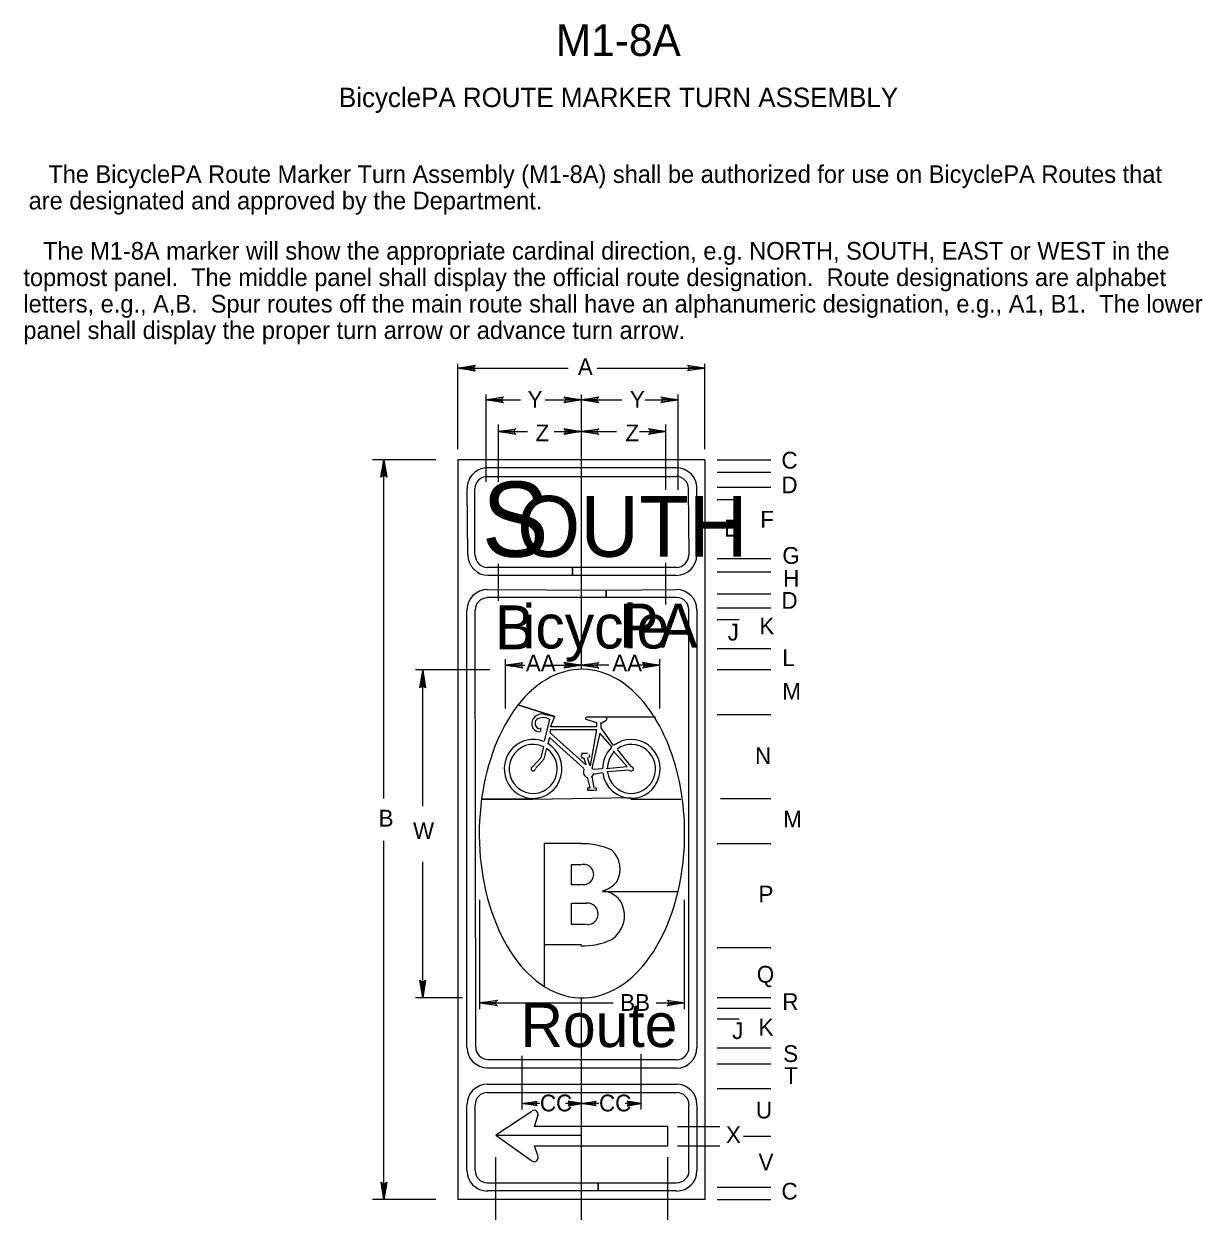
# Model space of a CAD drawing. Extents: x 0.013 to 0.193, y 0.004 to 0.259.
# Drawn here: x 0.0257 to 0.1928, y 0.091 to 0.2593 of the extents above; entities that cross this region are included whole.
import ezdxf

# ---------------------------------------------------------------- set-up
doc = ezdxf.new("R2010")
doc.units = 0
for name, color, linetype in [('1', 7, 'Continuous'), ('2', 7, 'Continuous'), ('3', 7, 'Continuous')]:
    doc.layers.add(name, color=color, linetype=linetype)

# ---------------------------------------------------------------- blocks, each defined once
blk = doc.blocks.new('RARROW')
at = {"layer": '3'}
for p, q in [((-2.156, 0.28500000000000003), (-2.2665, 0.384625)), ((-2.2665, 0.384625), (0, 0)), ((0, 0), (-2.2665, -0.379125)), ((-2.156, 0.28500000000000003), (-2.075625, 0.12075)), ((0, 0), (-2.156, 0.28500000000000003)), ((-2.14975, -0.2705), (0, 0)), ((-2.075625, 0.12075), (0, 0)), ((0, 0), (-2.074, -0.108)), ((-2.2665, -0.379125), (-2.14975, -0.2705)), ((-2.074, -0.108), (-2.14975, -0.2705))]:
    blk.add_line(p, q, dxfattribs=at)

msp = doc.modelspace()

# ---------------------------------------------------------------- linework, layer by layer
at = {"layer": '3'}
for p, q in [((0.08725000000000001, 0.199), (0.08725000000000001, 0.211125)), ((0.08725000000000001, 0.2105), (0.10287500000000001, 0.2105)), ((0.107, 0.2105), (0.12225, 0.2105)), ((0.12225, 0.199), (0.12225, 0.211125)), ((0.09125, 0.194375), (0.09125, 0.20675000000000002)), ((0.09125, 0.20600000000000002), (0.096125, 0.20600000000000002)), ((0.099625, 0.20600000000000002), (0.10475, 0.20600000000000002)), ((0.10475, 0.199875), (0.10475, 0.20675000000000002)), ((0.10475, 0.20600000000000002), (0.1105, 0.20600000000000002)), ((0.11375, 0.20600000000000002), (0.11850000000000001, 0.20600000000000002)), ((0.11850000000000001, 0.19325), (0.11850000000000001, 0.20675000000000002)), ((0.093, 0.194375), (0.093, 0.2025)), ((0.11675, 0.19325), (0.11675, 0.2025)), ((0.093, 0.2015), (0.097125, 0.2015)), ((0.100875, 0.2015), (0.10475, 0.2015)), ((0.10475, 0.2015), (0.10975, 0.2015)), ((0.113, 0.2015), (0.11675, 0.2015)), ((0.10475, 0.16775), (0.10475, 0.199875)), ((0.084125, 0.1975), (0.075125, 0.1975)), ((0.07675, 0.1495), (0.07675, 0.1975)), ((0.12225, 0.1975), (0.08725000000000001, 0.1975)), ((0.08725000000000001, 0.1975), (0.08725000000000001, 0.092625)), ((0.12225, 0.1975), (0.12225, 0.092625)), ((0.124, 0.1975), (0.131625, 0.1975)), ((0.11825000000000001, 0.196375), (0.0915, 0.196375)), ((0.124, 0.19575), (0.131625, 0.19575)), ((0.091375, 0.195125), (0.11812500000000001, 0.195125)), ((0.124, 0.193625), (0.131625, 0.193625)), ((0.0885, 0.193375), (0.088625, 0.184)), ((0.089625, 0.184), (0.089625, 0.193375)), ((0.11987500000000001, 0.193375), (0.12, 0.184)), ((0.121125, 0.184), (0.121125, 0.1935)), ((0.124, 0.19187500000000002), (0.12712500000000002, 0.19187500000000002)), ((0.093, 0.1775), (0.093, 0.18275)), ((0.11675, 0.177), (0.11675, 0.182875)), ((0.124, 0.1835), (0.131625, 0.1835)), ((0.124, 0.181625), (0.131625, 0.181625)), ((0.091375, 0.179125), (0.10825, 0.179)), ((0.124, 0.1785), (0.131625, 0.1785)), ((0.0885, 0.11425), (0.0885, 0.17625)), ((0.089625, 0.17625), (0.08975, 0.11425)), ((0.12, 0.11425), (0.12, 0.17625)), ((0.121125, 0.17625), (0.121125, 0.11425)), ((0.124, 0.1765), (0.131625, 0.1765)), ((0.124, 0.174875), (0.12712500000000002, 0.174875)), ((0.124, 0.17075), (0.131625, 0.17075)), ((0.094, 0.16225), (0.094, 0.16925)), ((0.094, 0.168375), (0.09675, 0.168375)), ((0.1005, 0.168375), (0.10475, 0.168375)), ((0.108625, 0.168375), (0.10475, 0.168375)), ((0.115875, 0.168375), (0.112875, 0.168375)), ((0.115875, 0.16225), (0.115875, 0.16925)), ((0.08125, 0.16775), (0.09175, 0.16775)), ((0.08225, 0.148375), (0.08225, 0.16775)), ((0.124, 0.16775), (0.131625, 0.16775)), ((0.101, 0.161125), (0.09575, 0.16275)), ((0.09575, 0.16275), (0.101, 0.161125)), ((0.09575, 0.16275), (0.09575, 0.16275)), ((0.099875, 0.161375), (0.09925, 0.1615)), ((0.09925, 0.1615), (0.101, 0.161125)), ((0.10025, 0.16075), (0.0995, 0.15762500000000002)), ((0.100375, 0.15962500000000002), (0.101, 0.161125)), ((0.105375, 0.16075), (0.106875, 0.16025)), ((0.10825, 0.161), (0.1055, 0.161)), ((0.106875, 0.16025), (0.106875, 0.15962500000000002)), ((0.1075, 0.16025), (0.1075, 0.1595)), ((0.10825, 0.161), (0.10825, 0.161)), ((0.10825, 0.161), (0.10825, 0.161)), ((0.11525, 0.161), (0.10825, 0.161)), ((0.11525, 0.161), (0.10825, 0.161)), ((0.124, 0.161375), (0.131625, 0.161375)), ((0.099, 0.159), (0.099, 0.1595)), ((0.106875, 0.15962500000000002), (0.100375, 0.15962500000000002)), ((0.107375, 0.15875), (0.10625, 0.15375)), ((0.109125, 0.15675), (0.107375, 0.15875)), ((0.1075, 0.1595), (0.10925, 0.157)), ((0.099375, 0.15687500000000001), (0.099, 0.15525)), ((0.0995, 0.155125), (0.099875, 0.15662500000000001)), ((0.099875, 0.15662500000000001), (0.099875, 0.15662500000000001)), ((0.10025, 0.15812500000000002), (0.1, 0.15725)), ((0.105125, 0.15375), (0.10025, 0.15812500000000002)), ((0.109125, 0.15675), (0.109125, 0.15675)), ((0.099, 0.15525), (0.097875, 0.154)), ((0.09825, 0.15375), (0.0995, 0.155125)), ((0.105625, 0.155875), (0.10475, 0.155875)), ((0.11125, 0.154), (0.10925, 0.15625)), ((0.109875, 0.15637500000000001), (0.109875, 0.15637500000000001)), ((0.109875, 0.15637500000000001), (0.11175, 0.154)), ((0.105125, 0.15375), (0.105125, 0.15375)), ((0.1065, 0.153625), (0.10775, 0.15375)), ((0.10825, 0.15375), (0.11125, 0.154)), ((0.111625, 0.1535), (0.108375, 0.15325)), ((0.108375, 0.15325), (0.108375, 0.15325)), ((0.106, 0.151), (0.105625, 0.1525)), ((0.10625, 0.152625), (0.1065, 0.151)), ((0.10775, 0.153125), (0.1065, 0.152875)), ((0.105625, 0.151), (0.106, 0.151)), ((0.106625, 0.150625), (0.105625, 0.150625)), ((0.1065, 0.151), (0.106625, 0.151)), ((0.097875, 0.149375), (0.090625, 0.149375)), ((0.090625, 0.149375), (0.097875, 0.149375)), ((0.090625, 0.149375), (0.090625, 0.149375)), ((0.097875, 0.149375), (0.11175, 0.149625)), ((0.097875, 0.149375), (0.11175, 0.149625)), ((0.11175, 0.149375), (0.11887500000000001, 0.149375)), ((0.11175, 0.149375), (0.11887500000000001, 0.149375)), ((0.1245, 0.1495), (0.131625, 0.1495)), ((0.07675, 0.092625), (0.07675, 0.14350000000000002)), ((0.10475, 0.143125), (0.0995, 0.143125)), ((0.0995, 0.143125), (0.0995, 0.122875)), ((0.124, 0.143125), (0.131625, 0.143125)), ((0.08225, 0.12125), (0.08225, 0.1405)), ((0.10337500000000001, 0.13725), (0.10337500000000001, 0.140125)), ((0.10337500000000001, 0.140125), (0.10475, 0.140125)), ((0.10475, 0.13725), (0.10337500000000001, 0.13725)), ((0.090375, 0.11962500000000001), (0.090375, 0.135125)), ((0.11850000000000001, 0.13625), (0.10775, 0.13625)), ((0.11825000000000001, 0.13625), (0.10775, 0.13625)), ((0.11850000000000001, 0.13625), (0.11825000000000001, 0.13625)), ((0.11937500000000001, 0.11962500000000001), (0.11937500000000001, 0.135125)), ((0.10337500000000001, 0.134625), (0.1055, 0.134625)), ((0.10337500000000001, 0.131625), (0.10337500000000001, 0.134625)), ((0.1055, 0.131625), (0.10337500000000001, 0.131625)), ((0.10475, 0.12875), (0.0995, 0.12875)), ((0.0995, 0.12875), (0.0995, 0.122875)), ((0.124, 0.128375), (0.131625, 0.128375)), ((0.08125, 0.12125), (0.08787500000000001, 0.12125)), ((0.10475, 0.088), (0.10475, 0.12125)), ((0.124, 0.12125), (0.131625, 0.12125)), ((0.090375, 0.1205), (0.10925, 0.1205)), ((0.115375, 0.1205), (0.11937500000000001, 0.1205)), ((0.124, 0.11975000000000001), (0.131625, 0.11975000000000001)), ((0.124, 0.11825000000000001), (0.12712500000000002, 0.11825000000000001)), ((0.096375, 0.105375), (0.096375, 0.113)), ((0.11325, 0.105375), (0.11325, 0.11325)), ((0.124, 0.114125), (0.131625, 0.114125)), ((0.11825000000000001, 0.11125), (0.091375, 0.11125)), ((0.0915, 0.1125), (0.11825000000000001, 0.1125)), ((0.124, 0.111875), (0.131625, 0.111875)), ((0.091375, 0.109), (0.11825000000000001, 0.109)), ((0.11825000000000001, 0.10775), (0.091375, 0.10775)), ((0.124, 0.108375), (0.131625, 0.108375)), ((0.098875, 0.10625), (0.096375, 0.10625)), ((0.10725, 0.10625), (0.10251744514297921, 0.10625)), ((0.11325, 0.10625), (0.11096930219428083, 0.10625)), ((0.0885, 0.09675), (0.0885, 0.106)), ((0.089625, 0.106), (0.089625, 0.09675)), ((0.12, 0.09675), (0.12, 0.106)), ((0.121125, 0.106), (0.121125, 0.09675)), ((0.11837500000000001, 0.10300000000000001), (0.124375, 0.10300000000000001)), ((0.092625, 0.10175000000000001), (0.10475, 0.10175000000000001)), ((0.12775, 0.10162500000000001), (0.131625, 0.10162500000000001)), ((0.11837500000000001, 0.10025), (0.124375, 0.10025)), ((0.092625, 0.085625), (0.092625, 0.098625)), ((0.117, 0.085625), (0.117, 0.098625)), ((0.091375, 0.095), (0.107125, 0.095)), ((0.124, 0.094375), (0.131625, 0.094375)), ((0.084125, 0.092625), (0.075125, 0.092625)), ((0.12225, 0.092625), (0.08725000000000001, 0.092625)), ((0.124, 0.092625), (0.131625, 0.092625))]:
    msp.add_line(p, q, dxfattribs=at)
for points in [[(0.0915, 0.181125), (0.10350000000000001, 0.181125), (0.10350000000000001, 0.18225), (0.091375, 0.18225)], [(0.11825000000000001, 0.18225), (0.10350000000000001, 0.18225), (0.10350000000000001, 0.181125), (0.11812500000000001, 0.181125)], [(0.10825, 0.179), (0.10825, 0.178), (0.091375, 0.178)], [(0.11825000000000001, 0.178), (0.10825, 0.178), (0.10825, 0.179), (0.11825000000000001, 0.179125)], [(0.10475, 0.15525), (0.105125, 0.15525), (0.105375, 0.15425), (0.100375, 0.15875), (0.100375, 0.15925), (0.106875, 0.15925)], [(0.106875, 0.15925), (0.106, 0.154125), (0.105625, 0.15525), (0.105625, 0.15525)], [(0.09775, 0.105125), (0.092625, 0.10175000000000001), (0.09775, 0.098125)], [(0.117, 0.10025), (0.117, 0.10300000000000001), (0.098125, 0.10300000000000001), (0.098625, 0.104625)], [(0.098625, 0.09875), (0.098125, 0.10025), (0.117, 0.10025)], [(0.107125, 0.095), (0.107125, 0.093875), (0.091375, 0.093875)], [(0.11825000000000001, 0.093875), (0.107125, 0.093875), (0.107125, 0.095), (0.11825000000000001, 0.095)]]:
    msp.add_lwpolyline(points, dxfattribs=at)
for centre, radius, start, end in [((0.09148619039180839, 0.193430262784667), 0.0029423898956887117, 88.92133055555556, 180), ((0.11824387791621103, 0.19344511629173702), 0.0029123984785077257, 0, 90), ((0.09140801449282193, 0.19338617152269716), 0.0017474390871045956, 90, 180), ((0.11819550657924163, 0.19342179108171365), 0.0017315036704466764, 359.423925, 89.42392500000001), ((0.0915507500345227, 0.18403872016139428), 0.0029123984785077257, 180, 270), ((0.09143824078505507, 0.1839948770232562), 0.0017474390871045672, 180, 270), ((0.11821094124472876, 0.18402065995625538), 0.0029123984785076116, 270, 0), ((0.11823230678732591, 0.1839948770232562), 0.001747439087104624, 270, 0), ((0.09143824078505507, 0.17618964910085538), 0.002912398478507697, 90, 180), ((0.11823230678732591, 0.17618964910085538), 0.0029123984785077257, 0, 90), ((0.09143824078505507, 0.17618964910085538), 0.0017474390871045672, 90, 180), ((0.11825007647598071, 0.17622635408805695), 0.0017474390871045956, 0, 90), ((0.09887221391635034, 0.16009801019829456), 0.0011653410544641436, 159.16154444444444, 272.64576666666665), ((0.09924986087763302, 0.1598801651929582), 0.0015972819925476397, 93.5801888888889, 156.6766), ((0.09893226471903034, 0.16010880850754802), 0.0007575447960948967, 112.33130277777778, 268.05661388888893), ((0.09934473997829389, 0.15919240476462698), 0.001756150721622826, 60.59737777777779, 112.67573055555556), ((0.10496961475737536, 0.13340940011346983), 0.00966476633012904, 64.91580277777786, 91.7117472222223), ((0.1066548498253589, 0.13948406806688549), 0.0036046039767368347, 329.89579722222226, 47.99597777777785), ((0.10506956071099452, 0.13870926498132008), 0.0014274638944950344, 261.5001972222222, 98.49980277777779), ((0.10648117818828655, 0.1405350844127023), 0.004360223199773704, 287.0058444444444, 319.02734722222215), ((0.10754082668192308, 0.13303015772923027), 0.0033423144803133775, 27.545941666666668, 86.30179444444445), ((0.10559536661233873, 0.13312787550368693), 0.001528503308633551, 270.00161944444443, 95.1911), ((0.10679450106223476, 0.13289040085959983), 0.004074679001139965, 303.89755, 24.43358055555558), ((0.10496961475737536, 0.13826151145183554), 0.009664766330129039, 268.2882527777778, 295.08419722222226), ((0.09143824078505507, 0.11421380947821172), 0.0029123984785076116, 180, 270), ((0.09151023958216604, 0.11423761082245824), 0.0017474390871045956, 180, 270), ((0.11825630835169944, 0.11419217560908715), 0.0017474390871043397, 270, 0), ((0.11823480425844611, 0.1141570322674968), 0.002910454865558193, 271.11779722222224, 1.1177972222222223), ((0.09143824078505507, 0.10605909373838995), 0.002912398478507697, 90, 180), ((0.09143824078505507, 0.10605909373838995), 0.0017474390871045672, 90, 180), ((0.11823230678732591, 0.10605909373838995), 0.0029123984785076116, 0, 90), ((0.11825370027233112, 0.10603770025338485), 0.0017689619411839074, 0.6929416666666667, 90.69294166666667), ((0.09806806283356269, 0.10474094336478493), 0.0005358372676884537, 341.94845833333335, 124.34720833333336), ((0.09806806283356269, 0.0985252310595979), 0.0005358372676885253, 235.23925833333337, 17.68419166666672), ((0.09143824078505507, 0.09673941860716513), 0.0029123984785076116, 180, 270), ((0.09143824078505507, 0.09673941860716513), 0.001747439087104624, 180, 270), ((0.11823230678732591, 0.09673941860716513), 0.002912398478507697, 270, 0), ((0.11825370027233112, 0.09676081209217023), 0.0017689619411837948, 269.3070583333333, 359.3070583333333)]:
    msp.add_arc(centre, radius, start, end, dxfattribs=at)
for centre, major_axis, ratio, start_param, end_param in [((0.10483527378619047, 0.14450275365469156), (1.4266637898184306e-18, 0.0232991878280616), 0.6249999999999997, 5.495524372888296, 6.964212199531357), ((0.10483527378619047, 0.14450275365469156), (1.4266637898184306e-18, 0.0232991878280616), 0.6249999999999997, 0.6810429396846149, 1.3549990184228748), ((0.10542463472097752, 0.1608296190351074), (6.81501369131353e-21, 0.00011129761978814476), 0.9804052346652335, 0, 2.7964537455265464), ((0.10599139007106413, 0.16370869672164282), (-7.139456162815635e-19, -0.0038865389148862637), 0.9804052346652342, 0.3922214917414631, 0.6561810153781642), ((0.10823507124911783, 0.16077397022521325), (-3.0667561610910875e-20, -0.0001669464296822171), 0.9804052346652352, 0.5182421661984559, 3.141592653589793), ((0.10483527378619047, 0.14450275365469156), (1.4266637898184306e-18, 0.0232991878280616), 0.6249999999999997, 4.927689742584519, 5.4955178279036), ((0.09791032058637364, 0.15367874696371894), (2.5556301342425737e-19, 0.004173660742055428), 0.980405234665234, 5.90428067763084, 9.426492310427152), ((0.09791032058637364, 0.15367874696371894), (2.1296917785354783e-19, 0.003478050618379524), 0.9804052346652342, 5.8372009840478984, 11.962836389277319), ((0.09791032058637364, 0.15367874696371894), (2.5556301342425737e-19, 0.004173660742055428), 0.980405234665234, 3.1432242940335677, 5.749303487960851), ((0.11184874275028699, 0.15367874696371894), (2.5556301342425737e-19, 0.004173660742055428), 0.980405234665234, 0.7638517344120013, 1.583042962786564), ((0.11184874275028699, 0.15367874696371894), (2.1296917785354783e-19, 0.003478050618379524), 0.9804052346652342, 1.7079627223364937, 6.913561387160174), ((0.11184874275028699, 0.15367874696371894), (2.5556301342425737e-19, 0.004173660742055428), 0.980405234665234, 3.1582208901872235, 6.92157007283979), ((0.10485261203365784, 0.1555242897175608), (1.0686641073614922e-20, 0.00017452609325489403), 0.980405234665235, 6.198627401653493, 9.509335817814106), ((0.10578888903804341, 0.15553448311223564), (1.0686641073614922e-20, 0.00017452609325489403), 0.980405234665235, 3.057034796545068, 6.187256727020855), ((0.11184874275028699, 0.15367874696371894), (2.1296917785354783e-19, 0.003478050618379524), 0.9804052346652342, 0.7848713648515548, 1.5684358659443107), ((0.09791032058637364, 0.15367874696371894), (1.8826475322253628e-20, 0.0003074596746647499), 0.9804052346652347, 0.2825696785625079, 4.644742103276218), ((0.10578867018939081, 0.15321825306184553), (4.7130035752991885e-20, 0.0007696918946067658), 0.9804052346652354, 0.9898988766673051, 3.006996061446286), ((0.10578867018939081, 0.15321825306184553), (4.7130035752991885e-20, 0.0007696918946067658), 0.9804052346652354, 5.179197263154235, 5.449443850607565), ((0.11184874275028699, 0.15367874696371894), (1.8826475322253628e-20, 0.0003074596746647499), 0.9804052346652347, 2.3681356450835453, 6.55357316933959), ((0.10578867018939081, 0.15321825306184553), (4.7130035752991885e-20, 0.0007696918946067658), 0.9804052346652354, 3.623585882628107, 4.496485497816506), ((0.11184874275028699, 0.15367874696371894), (2.5556301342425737e-19, 0.004173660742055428), 0.980405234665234, 1.7006056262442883, 3.158212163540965), ((0.10578785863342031, 0.15080587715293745), (1.0686641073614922e-20, 0.00017452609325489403), 0.980405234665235, 6.198627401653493, 9.509335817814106), ((0.10675034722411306, 0.15080587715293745), (1.0686641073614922e-20, 0.00017452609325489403), 0.980405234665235, 3.0570347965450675, 6.36774321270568), ((0.10483527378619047, 0.14450275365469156), (1.4266637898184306e-18, 0.0232991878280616), 0.6249999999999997, 1.3561330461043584, 2.77126399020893), ((0.10483527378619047, 0.14450275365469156), (1.4266637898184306e-18, 0.0232991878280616), 0.6249999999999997, 4.355608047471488, 4.9260615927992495), ((0.10483527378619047, 0.14450275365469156), (1.4266637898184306e-18, 0.0232991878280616), 0.6249999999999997, 2.771276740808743, 4.3556411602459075)]:
    msp.add_ellipse(centre, major_axis=major_axis, ratio=ratio, start_param=start_param, end_param=end_param, dxfattribs=at)

# ---------------------------------------------------------------- block references
for p, xscale, yscale, rotation in [((0.08725000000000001, 0.2105), 0.0010855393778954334, 0.0010738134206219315, 180), ((0.09125, 0.20600000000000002), 0.0010855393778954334, 0.0010738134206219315, 180), ((0.10475, 0.20600000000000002), 0.0010855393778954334, 0.0010738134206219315, 180), ((0.093, 0.2015), 0.0010855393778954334, 0.0010738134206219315, 180), ((0.10475, 0.2015), 0.0010855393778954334, 0.0010738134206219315, 180), ((0.07675, 0.1975), 0.0010855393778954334, 0.0010738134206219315, 90), ((0.094, 0.168375), 0.0010855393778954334, 0.0010738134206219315, 180), ((0.10475, 0.168375), 0.0010855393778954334, 0.0010738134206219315, 180), ((0.08225, 0.167625), 0.0010855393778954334, 0.0010738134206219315, 90), ((0.08225, 0.12125), 0.0010855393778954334, 0.0010738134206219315, -90.00000000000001), ((0.090375, 0.1205), 0.0010855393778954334, 0.0010738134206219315, 180), ((0.0965, 0.10625), 0.0008792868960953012, 0.0008697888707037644, 180), ((0.104875, 0.10625), 0.0008792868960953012, 0.0008697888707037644, 180), ((0.07675, 0.092625), 0.0010855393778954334, 0.0010738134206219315, -90.00000000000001)]:
    msp.add_blockref('RARROW', p, dxfattribs=dict(at, xscale=xscale, yscale=yscale, rotation=rotation))
for p, xscale, yscale in [((0.12225, 0.2105), 0.0010855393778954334, 0.0010738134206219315), ((0.10475, 0.20600000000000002), 0.0010855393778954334, 0.0010738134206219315), ((0.11850000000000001, 0.20600000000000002), 0.0010855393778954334, 0.0010738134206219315), ((0.10475, 0.2015), 0.0010855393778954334, 0.0010738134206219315), ((0.11675, 0.2015), 0.0010855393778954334, 0.0010738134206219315), ((0.10475, 0.168375), 0.0010855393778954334, 0.0010738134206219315), ((0.115875, 0.168375), 0.0010855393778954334, 0.0010738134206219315), ((0.11937500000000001, 0.1205), 0.0010855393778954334, 0.0010738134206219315), ((0.104875, 0.10625), 0.0008792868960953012, -0.0008697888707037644), ((0.11325, 0.10625), 0.0008792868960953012, -0.0008697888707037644)]:
    msp.add_blockref('RARROW', p, dxfattribs=dict(at, xscale=xscale, yscale=yscale))

# ---------------------------------------------------------------- texts
at = {"layer": '1'}
for s, height, p in [('M1-8A', 0.0045000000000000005, (0.101125, 0.25475000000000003)), ('BicyclePA ROUTE MARKER TURN ASSEMBLY', 0.00275025, (0.07037500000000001, 0.2475))]:
    msp.add_text(s, height=height, dxfattribs=at).set_placement(p)
at = {"layer": '2'}
for s, p in [('   The BicyclePA Route Marker Turn Assembly (M1-8A) shall be authorized for use on BicyclePA Routes that', (0.026375, 0.23675000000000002)), ('are designated and approved by the Department.', (0.026375, 0.233)), ('   The M1-8A marker will show the appropriate cardinal direction, e.g. NORTH, SOUTH, EAST or WEST in the', (0.025625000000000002, 0.22587475)), ('topmost panel.  The middle panel shall display the official route designation.  Route designations are alphabet', (0.025625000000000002, 0.22212500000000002)), ('letters, e.g., A,B.  Spur routes off the main route shall have an alphanumeric designation, e.g., A1, B1.  The lower', (0.025625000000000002, 0.21837525)), ('panel shall display the proper turn arrow or advance turn arrow.', (0.025625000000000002, 0.2146255))]:
    msp.add_text(s, height=0.0024997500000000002, dxfattribs=at).set_placement(p)
at = {"layer": '3'}
for s, height, p in [('A', 0.0023752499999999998, (0.10425, 0.2095)), ('Y', 0.0023752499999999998, (0.097125, 0.204875)), ('Y', 0.0023752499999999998, (0.111625, 0.204875)), ('Z', 0.0023752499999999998, (0.09825, 0.200125)), ('Z', 0.0023752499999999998, (0.111, 0.200125)), ('C', 0.0023752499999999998, (0.133125, 0.19625)), ('S', 0.01065225, (0.090625, 0.18375)), ('D', 0.0023752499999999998, (0.133125, 0.19275)), ('OUTH', 0.00862725, (0.095625, 0.18375)), ('F', 0.0023752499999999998, (0.130125, 0.18787500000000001)), ('E', 0.0023752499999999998, (0.125, 0.186625)), ('G', 0.0023752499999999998, (0.13325, 0.18275)), ('H', 0.0023752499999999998, (0.133375, 0.1795)), ('D', 0.0023752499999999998, (0.133125, 0.176375)), ('B', 0.0062325, (0.0925, 0.170625)), ('icycle', 0.00623325, (0.096375, 0.17075)), ('PA', 0.00623325, (0.110125, 0.170875)), ('K', 0.0023752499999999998, (0.13, 0.17275000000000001)), ('J', 0.0023752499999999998, (0.1255, 0.171875)), ('L', 0.0023752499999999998, (0.13325, 0.16825)), ('AA', 0.0023752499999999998, (0.096875, 0.1675)), ('AA', 0.0023752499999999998, (0.109125, 0.1675)), ('M', 0.0023752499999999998, (0.13325, 0.1635)), ('N', 0.0023752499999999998, (0.129375, 0.154375)), ('B', 0.0023752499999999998, (0.076, 0.1455)), ('M', 0.0023752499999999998, (0.133375, 0.145375)), ('W', 0.0023752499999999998, (0.080875, 0.14375000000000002)), ('P', 0.0023752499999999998, (0.129875, 0.13475)), ('Q', 0.0023752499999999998, (0.129625, 0.123375)), ('BB', 0.0023752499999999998, (0.11025, 0.11937500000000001)), ('R', 0.0023752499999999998, (0.13325, 0.11950000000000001)), ('Route', 0.00623325, (0.096125, 0.11425)), ('K', 0.0023752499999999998, (0.129875, 0.115875)), ('J', 0.0023752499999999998, (0.12612500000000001, 0.115375)), ('S', 0.0023752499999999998, (0.133375, 0.112125)), ('T', 0.0023752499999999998, (0.1335, 0.109)), ('CC', 0.0023752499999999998, (0.098875, 0.105125)), ('CC', 0.0023752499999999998, (0.10725, 0.105125)), ('U', 0.0023752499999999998, (0.1295, 0.104125)), ('X', 0.0023752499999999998, (0.12525, 0.100625)), ('V', 0.0023752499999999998, (0.129875, 0.09675)), ('C', 0.0023752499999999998, (0.133125, 0.092625))]:
    msp.add_text(s, height=height, dxfattribs=at).set_placement(p)

doc.saveas('drawing.dxf')
